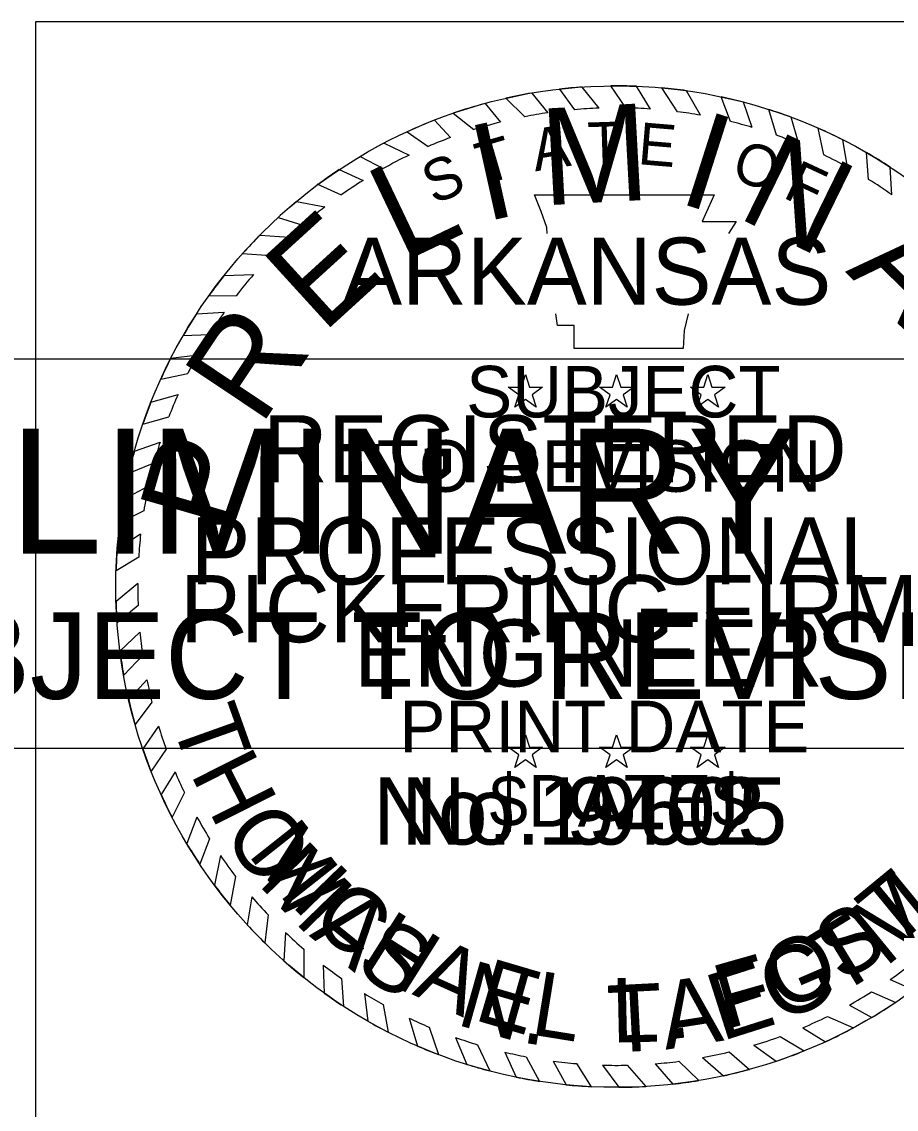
# Model space of a CAD drawing. Extents: x -0.68 to 1.92, y 0 to 0.95.
# Drawn here: x 1.2506 to 1.3416, y 0.0904 to 0.2035 of the extents above; entities that cross this region are included whole.
import ezdxf

# ---------------------------------------------------------------- set-up
doc = ezdxf.new("R2010")
doc.units = 0
for name, color, linetype in [('SHET_Stamp-Prelim', 7, 'Continuous'), ('STAMP_PE_BACKGROUND', 7, 'Continuous'), ('STAMP_PE_FOSTER', 7, 'Continuous'), ('STAMP_PE_SEAL-INFO', 7, 'Continuous'), ('STAMP_PE_TAEGTMEYER', 7, 'Continuous'), ('STAMP_PRELIMINARY', 7, 'Continuous')]:
    doc.layers.add(name, color=color, linetype=linetype)

msp = doc.modelspace()

# ---------------------------------------------------------------- linework, layer by layer
at = {"layer": 'SHET_Stamp-Prelim'}
msp.add_lwpolyline([(1.2006351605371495, 0.127997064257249), (1.3818064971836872, 0.127997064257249), (1.3818064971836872, 0.16844934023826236), (1.2006351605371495, 0.16844934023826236)], close=True, dxfattribs=at)
at = {"layer": 'STAMP_PE_BACKGROUND'}
msp.add_lwpolyline([(1.3712499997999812, 0.20354166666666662), (1.2520833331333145, 0.20354166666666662), (1.2520833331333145, 0.08437499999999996), (1.3712499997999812, 0.08437499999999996)], close=True, dxfattribs=at)
at = {"layer": 'STAMP_PE_SEAL-INFO'}
for p, q in [((1.3134475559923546, 0.19457995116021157), (1.3118903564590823, 0.19687143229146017)), ((1.3160059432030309, 0.19446539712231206), (1.314563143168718, 0.19683412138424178)), ((1.303677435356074, 0.19612232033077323), (1.3053475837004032, 0.19407263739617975)), ((1.3065572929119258, 0.19653485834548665), (1.3081281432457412, 0.1943966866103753)), ((1.3106664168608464, 0.19455519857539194), (1.3089229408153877, 0.1967520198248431)), ((1.3188309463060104, 0.1941848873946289), (1.3171991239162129, 0.196662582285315)), ((1.3212101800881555, 0.1938212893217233), (1.3197727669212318, 0.19636472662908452)), ((1.3243517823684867, 0.1931580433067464), (1.3233797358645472, 0.1957259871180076)), ((1.2988145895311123, 0.19504485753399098), (1.3004232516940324, 0.19310236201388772)), ((1.3009818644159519, 0.19558542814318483), (1.302970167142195, 0.19366858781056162)), ((1.326595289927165, 0.19255246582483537), (1.3257055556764, 0.19517308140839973)), ((1.2955130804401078, 0.19402700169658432), (1.297640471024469, 0.192320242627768)), ((1.3291194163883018, 0.19173382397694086), (1.328330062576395, 0.1944110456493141)), ((1.331456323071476, 0.19083978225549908), (1.330649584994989, 0.19361037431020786)), ((1.2935701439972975, 0.19331314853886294), (1.295216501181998, 0.19149339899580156)), ((1.334033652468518, 0.18969236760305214), (1.3334594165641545, 0.19247160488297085)), ((1.2907339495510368, 0.19210881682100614), (1.2929100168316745, 0.19057379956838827)), ((1.3365237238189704, 0.1884108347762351), (1.3360376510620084, 0.1912529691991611)), ((1.2883261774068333, 0.19092516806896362), (1.2909151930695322, 0.18966779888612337)), ((1.2858233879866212, 0.18952456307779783), (1.288237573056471, 0.18827851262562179)), ((1.3386891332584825, 0.18714612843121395), (1.3384674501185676, 0.18993992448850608)), ((1.2836624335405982, 0.18816295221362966), (1.2861302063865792, 0.187033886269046)), ((1.3411167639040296, 0.185545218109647), (1.3409425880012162, 0.18842299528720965)), ((1.281313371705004, 0.1866731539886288), (1.2838591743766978, 0.1855283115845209)), ((1.3039685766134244, 0.18552625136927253), (1.3226514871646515, 0.18552625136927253)), ((1.3046465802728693, 0.18380893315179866), (1.3039685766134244, 0.18552625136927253)), ((1.3226514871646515, 0.18552625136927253), (1.3213951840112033, 0.18277854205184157)), ((1.2792080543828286, 0.18484563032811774), (1.2821648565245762, 0.1842828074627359)), ((1.3052273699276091, 0.18214612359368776), (1.3046465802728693, 0.18380893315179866)), ((1.277287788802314, 0.1831684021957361), (1.2798508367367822, 0.1823922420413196)), ((1.3052674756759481, 0.18150686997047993), (1.3052273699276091, 0.18214612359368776)), ((1.3213951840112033, 0.18277854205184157), (1.3249286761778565, 0.18277854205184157)), ((1.3249286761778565, 0.18277854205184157), (1.324119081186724, 0.18150686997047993)), ((1.2754139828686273, 0.18136079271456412), (1.2784538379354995, 0.18113213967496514)), ((1.2736106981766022, 0.17943695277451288), (1.2765244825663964, 0.17922324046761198)), ((1.27167949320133, 0.1771391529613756), (1.2747463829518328, 0.1772637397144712)), ((1.2701252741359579, 0.17507460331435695), (1.2729470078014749, 0.17504611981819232)), ((1.2688156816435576, 0.17315280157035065), (1.271698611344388, 0.17334018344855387)), ((1.3063358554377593, 0.17195943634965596), (1.3061890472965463, 0.17317435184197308)), ((1.3199533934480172, 0.17317435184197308), (1.3195182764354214, 0.1714442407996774)), ((1.308091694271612, 0.17195943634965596), (1.3063358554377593, 0.17195943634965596)), ((1.308091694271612, 0.16955519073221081), (1.308091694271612, 0.17195943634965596)), ((1.26744046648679, 0.17091277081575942), (1.2701728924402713, 0.17102498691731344)), ((1.3195182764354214, 0.1714442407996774), (1.3194308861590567, 0.16955519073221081)), ((1.2661496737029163, 0.16854710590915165), (1.2689330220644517, 0.16890990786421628)), ((1.3194308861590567, 0.16955519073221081), (1.308091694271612, 0.16955519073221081)), ((1.2650990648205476, 0.1663746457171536), (1.2679063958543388, 0.16695428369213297)), ((1.3025906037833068, 0.16554957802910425), (1.3030139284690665, 0.16685243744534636)), ((1.3030139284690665, 0.16685243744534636), (1.303437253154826, 0.16554957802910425)), ((1.3120766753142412, 0.16554957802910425), (1.3125000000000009, 0.16685243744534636)), ((1.3125000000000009, 0.16685243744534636), (1.3129233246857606, 0.16554957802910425)), ((1.3215627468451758, 0.16554957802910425), (1.3219860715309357, 0.16685243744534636)), ((1.3219860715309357, 0.16685243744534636), (1.322409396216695, 0.16554957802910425)), ((1.3023289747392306, 0.1647443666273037), (1.3012206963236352, 0.16554957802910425)), ((1.3012206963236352, 0.16554957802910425), (1.302590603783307, 0.16554957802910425)), ((1.303437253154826, 0.16554957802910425), (1.304807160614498, 0.16554957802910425)), ((1.304807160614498, 0.16554957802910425), (1.303698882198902, 0.1647443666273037)), ((1.3118150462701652, 0.1647443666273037), (1.3107067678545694, 0.16554957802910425)), ((1.3107067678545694, 0.16554957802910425), (1.3120766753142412, 0.16554957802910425)), ((1.3129233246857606, 0.16554957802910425), (1.3142932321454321, 0.16554957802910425)), ((1.3142932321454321, 0.16554957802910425), (1.3131849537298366, 0.1647443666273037)), ((1.3213011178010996, 0.1647443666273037), (1.3201928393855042, 0.16554957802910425)), ((1.3201928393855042, 0.16554957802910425), (1.3215627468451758, 0.16554957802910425)), ((1.322409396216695, 0.16554957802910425), (1.323779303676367, 0.16554957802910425)), ((1.323779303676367, 0.16554957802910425), (1.3226710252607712, 0.1647443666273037)), ((1.2640715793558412, 0.1639583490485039), (1.2668884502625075, 0.16477560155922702)), ((1.3019056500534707, 0.16344150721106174), (1.3023289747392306, 0.1647443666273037)), ((1.3030139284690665, 0.1642467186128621), (1.3019056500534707, 0.16344150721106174)), ((1.3041222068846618, 0.16344150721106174), (1.3030139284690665, 0.1642467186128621)), ((1.303698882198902, 0.1647443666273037), (1.3041222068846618, 0.16344150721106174)), ((1.3113917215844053, 0.16344150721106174), (1.3118150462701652, 0.1647443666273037)), ((1.3125000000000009, 0.1642467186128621), (1.3113917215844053, 0.16344150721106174)), ((1.3136082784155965, 0.16344150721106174), (1.3125000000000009, 0.1642467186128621)), ((1.3131849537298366, 0.1647443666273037), (1.3136082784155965, 0.16344150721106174)), ((1.32087779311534, 0.16344150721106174), (1.3213011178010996, 0.1647443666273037)), ((1.3219860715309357, 0.1642467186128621), (1.32087779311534, 0.16344150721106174)), ((1.323094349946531, 0.16344150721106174), (1.3219860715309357, 0.1642467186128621)), ((1.3226710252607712, 0.1647443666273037), (1.323094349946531, 0.16344150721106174)), ((1.263233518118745, 0.16168803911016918), (1.265938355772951, 0.16244908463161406)), ((1.2623581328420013, 0.15887949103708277), (1.26502498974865, 0.15982145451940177)), ((1.2617733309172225, 0.15660177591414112), (1.2643992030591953, 0.15767904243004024)), ((1.2638081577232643, 0.1552260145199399), (1.2612078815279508, 0.1538355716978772)), ((1.263328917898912, 0.1526641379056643), (1.2608402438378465, 0.1514206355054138)), ((1.2630005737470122, 0.15023022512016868), (1.2605604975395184, 0.14865970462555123)), ((1.2627970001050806, 0.14785482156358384), (1.2604421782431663, 0.14642164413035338)), ((1.2627036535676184, 0.14509988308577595), (1.2604402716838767, 0.14322376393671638)), ((1.262741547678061, 0.14282506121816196), (1.2605540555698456, 0.14101112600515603)), ((1.2629281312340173, 0.14005870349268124), (1.260852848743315, 0.1380651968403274)), ((1.2632160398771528, 0.13765987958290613), (1.2612386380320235, 0.1355750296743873)), ((1.2636557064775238, 0.1350959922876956), (1.261759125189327, 0.1330427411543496)), ((1.264178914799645, 0.13275655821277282), (1.2624336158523, 0.13043789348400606)), ((1.2648703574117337, 0.13025934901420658), (1.2632237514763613, 0.1279237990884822)), ((1.3025906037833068, 0.1280793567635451), (1.3030139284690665, 0.1293822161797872)), ((1.3030139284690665, 0.1293822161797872), (1.303437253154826, 0.1280793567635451)), ((1.3120766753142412, 0.1280793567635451), (1.3125000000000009, 0.1293822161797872)), ((1.3125000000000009, 0.1293822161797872), (1.3129233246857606, 0.1280793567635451)), ((1.3215627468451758, 0.1280793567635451), (1.3219860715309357, 0.1293822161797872)), ((1.3219860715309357, 0.1293822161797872), (1.322409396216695, 0.1280793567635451)), ((1.2656570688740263, 0.12789459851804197), (1.264083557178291, 0.12559474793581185)), ((1.3023289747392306, 0.12727414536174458), (1.3012206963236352, 0.1280793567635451)), ((1.3012206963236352, 0.1280793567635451), (1.302590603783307, 0.1280793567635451)), ((1.303437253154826, 0.1280793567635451), (1.304807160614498, 0.1280793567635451)), ((1.304807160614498, 0.1280793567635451), (1.303698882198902, 0.12727414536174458)), ((1.3118150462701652, 0.12727414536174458), (1.3107067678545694, 0.1280793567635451)), ((1.3107067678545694, 0.1280793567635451), (1.3120766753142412, 0.1280793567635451)), ((1.3129233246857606, 0.1280793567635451), (1.3142932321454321, 0.1280793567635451)), ((1.3142932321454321, 0.1280793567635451), (1.3131849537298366, 0.12727414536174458)), ((1.3213011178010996, 0.12727414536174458), (1.3201928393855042, 0.1280793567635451)), ((1.3201928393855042, 0.1280793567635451), (1.3215627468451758, 0.1280793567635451)), ((1.322409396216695, 0.1280793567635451), (1.323779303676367, 0.1280793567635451)), ((1.323779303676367, 0.1280793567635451), (1.3226710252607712, 0.12727414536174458)), ((1.3019056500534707, 0.1259712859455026), (1.3023289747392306, 0.12727414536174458)), ((1.3030139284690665, 0.12677649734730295), (1.3019056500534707, 0.1259712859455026)), ((1.3041222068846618, 0.1259712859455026), (1.3030139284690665, 0.12677649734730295)), ((1.303698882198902, 0.12727414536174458), (1.3041222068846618, 0.1259712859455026)), ((1.3113917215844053, 0.1259712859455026), (1.3118150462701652, 0.12727414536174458)), ((1.3125000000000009, 0.12677649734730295), (1.3113917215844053, 0.1259712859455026)), ((1.3136082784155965, 0.1259712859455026), (1.3125000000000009, 0.12677649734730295)), ((1.3131849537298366, 0.12727414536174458), (1.3136082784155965, 0.1259712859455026)), ((1.32087779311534, 0.1259712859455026), (1.3213011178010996, 0.12727414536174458)), ((1.3219860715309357, 0.12677649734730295), (1.32087779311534, 0.1259712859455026)), ((1.323094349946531, 0.1259712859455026), (1.3219860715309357, 0.12677649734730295)), ((1.3226710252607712, 0.12727414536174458), (1.323094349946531, 0.1259712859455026)), ((1.2665856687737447, 0.12551356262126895), (1.2651242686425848, 0.12315342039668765)), ((1.267545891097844, 0.12336973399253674), (1.266273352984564, 0.12079644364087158)), ((1.268857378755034, 0.1208105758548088), (1.2677921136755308, 0.11807316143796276)), ((1.270174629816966, 0.11855554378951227), (1.269147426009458, 0.11592597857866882)), ((1.2713056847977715, 0.11681311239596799), (1.2706928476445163, 0.11372986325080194)), ((1.2728742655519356, 0.11463255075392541), (1.2723060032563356, 0.1116689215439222)), ((1.2745723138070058, 0.11252307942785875), (1.274087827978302, 0.10961811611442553)), ((1.276262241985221, 0.11063619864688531), (1.2759166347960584, 0.10771969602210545)), ((1.278064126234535, 0.10882026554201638), (1.2778977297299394, 0.10586408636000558)), ((1.2799881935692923, 0.10707226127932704), (1.2799693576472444, 0.10411697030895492)), ((1.2819988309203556, 0.10542861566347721), (1.2821035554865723, 0.10249828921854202)), ((1.2838901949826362, 0.1040332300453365), (1.2840915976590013, 0.10113807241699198)), ((1.3409364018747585, 0.10391206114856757), (1.3433867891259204, 0.10285504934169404)), ((1.2862754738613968, 0.10245911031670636), (1.2866141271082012, 0.09959658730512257)), ((1.3390154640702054, 0.1026407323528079), (1.3415267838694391, 0.10154678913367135)), ((1.288232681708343, 0.10130755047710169), (1.2887423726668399, 0.0984424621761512)), ((1.3367005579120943, 0.10127036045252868), (1.3390290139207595, 0.0999710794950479)), ((1.2909209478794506, 0.099912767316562), (1.291795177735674, 0.09700062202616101)), ((1.3344222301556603, 0.10007939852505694), (1.3371253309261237, 0.09889758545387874)), ((1.293001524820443, 0.09897048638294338), (1.2939672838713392, 0.09611711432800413)), ((1.3318569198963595, 0.09891050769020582), (1.3342210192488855, 0.09745382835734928)), ((1.2957537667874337, 0.09789460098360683), (1.2969220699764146, 0.09509255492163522)), ((1.329513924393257, 0.0979910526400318), (1.3319882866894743, 0.09649176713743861)), ((1.2980417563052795, 0.09713948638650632), (1.2993055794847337, 0.09440733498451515)), ((1.3008793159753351, 0.09636924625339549), (1.3020657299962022, 0.09376422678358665)), ((1.3241937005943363, 0.09638682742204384), (1.3263049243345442, 0.0945711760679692)), ((1.3267617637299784, 0.09708031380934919), (1.3290873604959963, 0.09542028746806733)), ((1.3030999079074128, 0.09588962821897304), (1.3044779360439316, 0.09332983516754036)), ((1.305895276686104, 0.09543430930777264), (1.3072346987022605, 0.0929751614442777)), ((1.3083340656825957, 0.0951689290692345), (1.3098657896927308, 0.09277499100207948)), ((1.316507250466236, 0.095155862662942), (1.3183272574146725, 0.09303534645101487)), ((1.318955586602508, 0.0954145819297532), (1.3210386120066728, 0.0934130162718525)), ((1.3214431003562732, 0.09580399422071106), (1.3236130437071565, 0.09390774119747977)), ((1.3110413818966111, 0.09501573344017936), (1.3127316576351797, 0.09270884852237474)), ((1.3136097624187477, 0.09500673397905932), (1.3155308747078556, 0.09279659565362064))]:
    msp.add_line(p, q, dxfattribs=at)
for radius, start, end in [(0.05208333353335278, 87.72978562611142, 90.67067134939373), (0.05208333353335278, 99.75254266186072, 102.77648138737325), (0.05208333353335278, 93.93814766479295, 96.55171575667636), (0.05208333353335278, 81.97315125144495, 84.82355346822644), (0.05208333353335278, 75.31251453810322, 77.94263429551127), (0.05208333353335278, 105.2338868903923, 109.03519250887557), (0.04979730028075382, 85.96279180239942, 88.90969519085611), (0.04979730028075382, 98.25798851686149, 101.03289140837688), (0.04979730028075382, 92.11016115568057, 95.0366553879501), (0.04979730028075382, 79.92642235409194, 82.69597271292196), (0.05208333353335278, 69.60611387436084, 72.30576523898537), (0.05208333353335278, 111.31242303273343, 114.70259160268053), (0.04979730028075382, 104.03521042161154, 107.3615463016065), (0.04979730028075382, 73.55748025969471, 76.23144174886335), (0.05208333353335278, 63.13287778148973, 66.27039835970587), (0.04979730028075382, 110.30863674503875, 113.1658795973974), (0.04979730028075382, 67.62482877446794, 70.50398398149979), (0.05208333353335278, 117.65440981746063, 120.8098782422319), (0.04979730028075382, 115.68691928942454, 119.15826889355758), (0.04979730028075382, 61.155754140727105, 64.37837449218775), (0.05208333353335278, 56.90029228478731, 60.09422987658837), (0.05208333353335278, 123.61993215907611, 126.59062794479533), (0.04979730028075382, 121.97455773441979, 125.1100085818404), (0.04979730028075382, 54.923827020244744, 58.27015777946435), (0.05208333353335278, 129.73259019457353, 132.53764328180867), (0.04979730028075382, 127.5296898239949, 130.96828939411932), (0.05208333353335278, 135.40207922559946, 138.30313604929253), (0.04979730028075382, 133.13305755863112, 136.25622701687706), (0.05208333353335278, 141.60555977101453, 144.4486483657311), (0.04979730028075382, 139.30101253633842, 142.58728849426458), (0.05208333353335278, 147.00719016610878, 149.8990425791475), (0.04979730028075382, 145.0197202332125, 148.2103639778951), (0.05208333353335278, 152.8639823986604, 155.51889127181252), (0.04979730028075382, 151.03152721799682, 153.57304034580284), (0.04979730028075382, 156.3401777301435, 159.23193612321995), (0.05208333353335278, 158.40765685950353, 161.07014519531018), (0.04979730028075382, 162.43309106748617, 165.00132712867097), (0.05208333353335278, 164.306798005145, 166.89395340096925), (0.04979730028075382, 167.9048137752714, 170.90393120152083), (0.05208333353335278, 170.00030285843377, 172.68777762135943), (0.04979730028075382, 173.72999663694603, 176.47336897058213), (0.05208333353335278, 175.7409317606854, 178.20660347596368), (0.04979730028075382, 179.64537030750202, 182.26332578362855), (0.05208333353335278, 181.72507764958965, 184.1625542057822), (0.04979730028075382, 185.45388553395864, 188.23400522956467), (0.05208333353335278, 187.4203742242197, 190.19270523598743), (0.04979730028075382, 191.22736344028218, 193.98583171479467), (0.05208333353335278, 193.03694969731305, 195.99732329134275), (0.04979730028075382, 196.96751323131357, 199.83526481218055), (0.05208333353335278, 198.89670805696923, 201.62812073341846), (0.04979730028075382, 202.77613115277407, 205.4791499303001), (0.05208333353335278, 204.54793110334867, 207.4328212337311), (0.04979730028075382, 208.78826076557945, 211.79343039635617), (0.05208333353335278, 210.86355209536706, 213.65709060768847), (0.04979730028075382, 214.1837527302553, 217.27473515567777), (0.05208333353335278, 216.6115448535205, 219.49097786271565), (0.04979730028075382, 220.3908842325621, 223.30563758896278), (0.05208333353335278, 222.47995056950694, 225.38007606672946), (0.04979730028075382, 226.24937804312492, 229.24068458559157), (0.05208333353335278, 228.36647999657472, 231.34802159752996), (0.04979730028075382, 232.22904076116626, 234.9336099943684), (0.04979730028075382, 304.8229923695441, 308.51427595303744), (0.05208333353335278, 234.2950242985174, 236.94517274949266), (0.04979730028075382, 238.22226702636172, 240.83528634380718), (0.04979730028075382, 299.0767860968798, 302.17235325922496), (0.05208333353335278, 300.6210136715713, 303.87026284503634), (0.05208333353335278, 240.19770246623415, 242.8612773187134), (0.04979730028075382, 244.32042796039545, 246.94859267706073), (0.04979730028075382, 292.87451949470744, 296.11851166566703), (0.05208333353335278, 294.64807577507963, 298.2166176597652), (0.04979730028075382, 250.34912199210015, 253.1215727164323), (0.04979730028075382, 286.6423316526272, 289.9782614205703), (0.05208333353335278, 246.5759811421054, 249.15579179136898), (0.04979730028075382, 256.50504644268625, 259.1191575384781), (0.04979730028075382, 280.345883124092, 283.58136600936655), (0.05208333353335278, 288.5708646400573, 291.9733383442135), (0.05208333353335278, 252.59666978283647, 255.3251775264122), (0.04979730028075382, 262.37827883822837, 265.2011504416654), (0.04979730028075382, 274.6156530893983, 277.44863267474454), (0.04979730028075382, 268.32150305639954, 271.2769761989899), (0.05208333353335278, 282.3199420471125, 285.3701939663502), (0.05208333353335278, 258.4432759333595, 261.13982575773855), (0.05208333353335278, 264.1978410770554, 267.1009237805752), (0.05208333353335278, 270.25484253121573, 273.33608620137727), (0.05208333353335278, 276.4238933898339, 279.4357408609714)]:
    msp.add_arc((1.3125000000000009, 0.14479166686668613), radius, start, end, dxfattribs=at)
at = {"layer": 'STAMP_PRELIMINARY'}
msp.add_circle((1.3125000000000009, 0.14479166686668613), 0.05208333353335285, dxfattribs=at)

# ---------------------------------------------------------------- texts
at = {"layer": 'SHET_Stamp-Prelim'}
for s, height, p in [('PRELIMINARY', 0.013, (1.2136081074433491, 0.14822320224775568)), ('SUBJECT TO REVISION', 0.009, (1.2267484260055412, 0.13311013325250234))]:
    msp.add_text(s, height=height, dxfattribs=at).set_placement(p)
at = {"layer": 'STAMP_PE_FOSTER'}
msp.add_text('No. 9402', height=0.006983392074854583, dxfattribs=at).set_placement((1.290073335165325, 0.11795939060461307))
for s, height, rotation, p in [('M', 0.006704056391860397, 308.3390181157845, (1.2740407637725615, 0.1169807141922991)), ('I', 0.006704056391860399, 314.1842317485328, (1.278497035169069, 0.1117434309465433)), ('T', 0.006704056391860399, 39.41937898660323, (1.3412284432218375, 0.1070258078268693)), ('C', 0.006704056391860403, 319.87326798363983, (1.2804759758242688, 0.10976998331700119)), ('H', 0.006704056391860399, 327.7234907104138, (1.2856674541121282, 0.10565603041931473)), ('S', 0.0067040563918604, 31.72335532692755, (1.3359121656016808, 0.10351874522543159)), ('A', 0.006704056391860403, 335.72761050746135, (1.2911454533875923, 0.102405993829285)), ('O', 0.006704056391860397, 23.718966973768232, (1.3297030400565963, 0.10055799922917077)), ('F', 0.0067040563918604, 15.869077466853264, (1.323868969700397, 0.09872769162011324)), ('E', 0.006704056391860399, 343.5779028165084, (1.2975022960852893, 0.09977820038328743)), ('L', 0.006704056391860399, 350.81147507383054, (1.3034155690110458, 0.09822763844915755)), ('L', 0.006704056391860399, 1.2665847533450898, (1.312016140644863, 0.09735221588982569)), ('.', 0.0067040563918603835, 6.803540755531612, (1.3178636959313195, 0.0976781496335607))]:
    msp.add_text(s, height=height, rotation=rotation, dxfattribs=at).set_placement(p)
at = {"layer": 'STAMP_PE_SEAL-INFO'}
for s, height, rotation, p in [('A', 0.004364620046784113, 9.067898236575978, (1.3040301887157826, 0.18797032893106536)), ('T', 0.0043646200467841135, 1.824794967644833, (1.3095417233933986, 0.18869363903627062)), ('E', 0.004364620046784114, 355.2001929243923, (1.3146261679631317, 0.18874179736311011)), ('T', 0.004364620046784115, 16.311001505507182, (1.298653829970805, 0.186557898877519)), ('O', 0.004364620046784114, 342.25064860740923, (1.324272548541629, 0.18719510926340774)), ('S', 0.004364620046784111, 23.55410477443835, (1.2934984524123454, 0.18447889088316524)), ('F', 0.0043646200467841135, 335.00754533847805, (1.329666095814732, 0.18530659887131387))]:
    msp.add_text(s, height=height, rotation=rotation, dxfattribs=at).set_placement(p)
for s, p in [('ARKANSAS', (1.2839647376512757, 0.17410696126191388)), ('REGISTERED', (1.2757208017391, 0.15563536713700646)), ('PROFESSIONAL', (1.2681887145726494, 0.14501247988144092)), ('ENGINEER', (1.2851749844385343, 0.13438959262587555))]:
    msp.add_text(s, height=0.006983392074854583, dxfattribs=at).set_placement(p)
at = {"layer": 'STAMP_PE_TAEGTMEYER'}
for s, height, rotation, p in [('T', 0.006983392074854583, 289.64596820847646, (1.2660987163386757, 0.13088211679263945)), ('H', 0.0069833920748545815, 296.73386139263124, (1.268109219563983, 0.12538216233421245)), ('O', 0.006983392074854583, 303.7707760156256, (1.2714213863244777, 0.1191922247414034)), ('M', 0.006983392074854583, 314.203293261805, (1.2750806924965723, 0.11387791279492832)), ('M', 0.00698339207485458, 39.30004668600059, (1.3404223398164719, 0.1051158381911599)), ('A', 0.006983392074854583, 321.05939598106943, (1.2804521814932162, 0.10848903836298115)), ('T', 0.00698339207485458, 31.466005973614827, (1.335405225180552, 0.10208014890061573)), ('S', 0.006983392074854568, 327.82385093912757, (1.2850689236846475, 0.10489215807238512)), ('G', 0.00698339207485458, 23.30524175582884, (1.3292590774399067, 0.09932653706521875)), ('N', 0.006983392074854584, 344.27272867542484, (1.2956650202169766, 0.09926973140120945)), ('E', 0.006983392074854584, 17.683629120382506, (1.3233935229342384, 0.09747987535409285)), ('A', 0.0069833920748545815, 8.9826070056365, (1.3175889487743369, 0.09661125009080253)), ('T', 0.006983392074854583, 3.006085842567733, (1.3117410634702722, 0.09630184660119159)), ('.', 0.0069833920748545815, 350.64642779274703, (1.3024405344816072, 0.09741494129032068))]:
    msp.add_text(s, height=height, rotation=rotation, dxfattribs=at).set_placement(p)
msp.add_text('No. 19605', height=0.006983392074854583, dxfattribs=at).set_placement((1.2871469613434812, 0.11795939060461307))
at = {"layer": 'STAMP_PRELIMINARY'}
for s, rotation, p in [('M', 3.107384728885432, (1.3048781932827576, 0.18443386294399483)), ('I', 342.3163708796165, (1.3186635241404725, 0.18481031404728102)), ('I', 12.524847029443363, (1.2987433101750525, 0.18270651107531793)), ('N', 333.93819993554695, (1.3248520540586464, 0.18327946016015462)), ('L', 25.513048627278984, (1.290202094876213, 0.17846557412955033)), ('E', 42.3578427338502, (1.2819189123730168, 0.17102941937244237)), ('A', 315.65789090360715, (1.3362148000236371, 0.17755060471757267)), ('R', 56.22922398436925, (1.2754632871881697, 0.16134985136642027)), ('P', 73.91301312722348, (1.2723945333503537, 0.15004546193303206))]:
    msp.add_text(s, height=0.010056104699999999, rotation=rotation, dxfattribs=at).set_placement(p)
for s, height, p in [('SUBJECT', 0.005363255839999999, (1.2968572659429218, 0.16238601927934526)), ('TO REVISION', 0.005363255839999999, (1.2875569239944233, 0.15465015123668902)), ('PICKERING FIRM', 0.006983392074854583, (1.2670979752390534, 0.1389994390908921)), ('PRINT DATE', 0.005363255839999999, (1.2899156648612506, 0.12755885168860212)), ('$DATE$', 0.005363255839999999, (1.299282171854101, 0.11982298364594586))]:
    msp.add_text(s, height=height, dxfattribs=at).set_placement(p)

doc.saveas('drawing.dxf')
